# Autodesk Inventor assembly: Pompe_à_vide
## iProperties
Shininess: 64.0
Length Units: 11269
Angle Units: 11279
Time Units: 11290
Mass Units: 11283
Length Display Precision: 3
Angle Display Precision: 2
Compacted: True
Created: 2005-01
Part Number: Pompe_à_vide
Document SubType Name: Assembly
Designer: MARTY
Density: 0.0
Volumn: 0.0
Area: 0.0
PropertySet Name: Model Information
Control State: 0
Master: False
Checked Out: False
Author: MARTY
